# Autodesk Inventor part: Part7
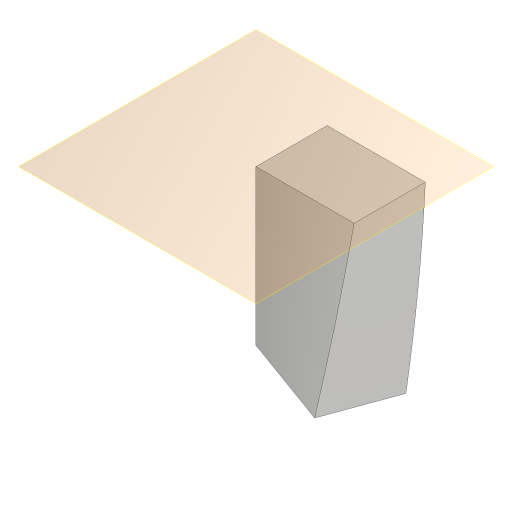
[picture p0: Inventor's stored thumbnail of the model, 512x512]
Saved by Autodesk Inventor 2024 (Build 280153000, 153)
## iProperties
Created: 2015-07
Part Number: Part7
Material: Generic
Document SubType Name: Modeling
Designer: Sandeep
Density: 1 g/cm^3
Appearance: Default
Author: Sandeep
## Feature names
1. Sweep1
## Parameters: d0 = 0, d1 = 20 deg
